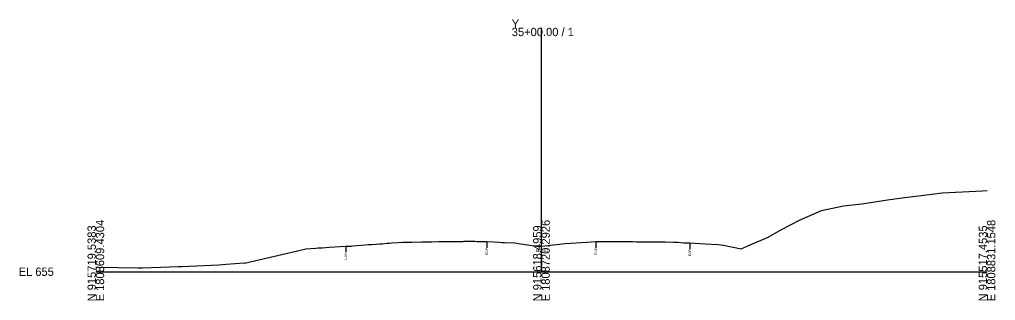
# Model space of a CAD drawing. Extents: x -26 to 3303, y -30 to 9580.
# Drawn here: x 1974.3 to 2302.8, y 4990.3 to 5085 of the extents above; entities that cross this region are included whole.
import ezdxf

# ---------------------------------------------------------------- set-up
doc = ezdxf.new("R2010")
doc.units = 0
for name, color, linetype in [('Exist Cross Section Cell', 7, 'Continuous'), ('Exist XS Center Line Elevation Label', 7, 'Continuous'), ('Exist XS Ground Line', 7, 'Continuous'), ('Old_Level_10', 7, 'Continuous')]:
    doc.layers.add(name, color=color, linetype=linetype)

msp = doc.modelspace()

# ---------------------------------------------------------------- linework, layer by layer
at = {"layer": 'Exist Cross Section Cell'}
for p, q in [((2150, 5000), (2150, 5082.17)), ((2000, 5000), (2150, 5000)), ((2150, 5000), (2300, 5000))]:
    msp.add_line(p, q, dxfattribs=at)
at = {"layer": 'Exist XS Ground Line'}
msp.add_lwpolyline([(2000, 5001.52), (2000.77, 5001.56), (2014.3, 5001.28), (2015.75, 5001.33), (2027.83, 5001.73), (2029.01, 5001.78), (2041.36, 5002.29), (2043.85, 5002.52), (2049.92, 5003.01), (2050.01, 5002.83), (2067.84, 5007.04), (2070.64, 5007.73), (2074.06, 5007.96), (2074.85, 5008.01), (2076.13, 5008.09), (2078.56, 5008.24), (2084.11, 5008.59), (2086.07, 5008.65), (2086.48, 5008.67), (2087.9, 5008.86), (2089.44, 5008.96), (2090.64, 5009.05), (2091.79, 5009.13), (2092.84, 5009.2), (2094.35, 5009.3), (2095.62, 5009.39), (2096.39, 5009.44), (2098.07, 5009.57), (2098.87, 5009.63), (2099.58, 5009.68), (2101.78, 5009.83), (2103.21, 5009.91), (2103.75, 5009.94), (2103.97, 5009.94), (2105.48, 5009.96), (2106.37, 5009.98), (2109.72, 5010.05), (2111.25, 5010.07), (2113.11, 5010.09), (2115.48, 5010.13), (2115.87, 5010.13), (2116.64, 5010.15), (2120.31, 5010.21), (2121.88, 5010.22), (2123.3, 5010.23), (2123.64, 5010.23), (2124.02, 5010.24), (2125.42, 5010.25), (2126.65, 5010.26), (2127.31, 5010.27), (2127.68, 5010.27), (2128.39, 5010.21), (2130.04, 5010.15), (2131.13, 5010.14), (2131.59, 5010.13), (2133.91, 5010.03), (2135.74, 5009.95), (2136.81, 5009.89), (2137.52, 5009.85), (2140.99, 5009.69), (2142.3, 5009.5), (2149.13, 5008.53), (2150, 5008.61), (2151.16, 5008.73), (2158.02, 5009.49), (2165.23, 5009.95), (2166.72, 5010.04), (2168.36, 5010.15), (2169.22, 5010.15), (2170.63, 5010.16), (2171.94, 5010.2), (2172.35, 5010.23), (2172.95, 5010.22), (2174.02, 5010.21), (2174.96, 5010.19), (2176, 5010.18), (2176.74, 5010.18), (2177.41, 5010.17), (2178.52, 5010.16), (2179.73, 5010.15), (2180.8, 5010.14), (2182.05, 5010.12), (2183.47, 5010.1), (2184.18, 5010.08), (2184.7, 5010.08), (2187.55, 5010.04), (2190.94, 5010.02), (2191.61, 5010.02), (2194.56, 5009.98), (2195.84, 5009.96), (2197.97, 5009.76), (2198.28, 5009.75), (2199.94, 5009.7), (2205.07, 5009.44), (2209.49, 5009.22), (2211.23, 5008.9), (2217.23, 5007.76), (2220.28, 5009.03), (2226.28, 5011.6), (2230.79, 5014.25), (2236.84, 5017.42), (2244.32, 5020.63), (2251.68, 5022.18), (2257.85, 5022.89), (2266.53, 5024.23), (2271.38, 5024.85), (2281.37, 5026.15), (2284.91, 5026.63), (2296.22, 5027.1), (2298.44, 5027.22), (2300, 5027.39)], dxfattribs=at)
at = {"layer": 'Old_Level_10'}
for p, q in [((2131.59, 5010.13), (2131.59, 5008.08)), ((2168.36, 5010.15), (2168.36, 5008.1)), ((2084.11, 5008.59), (2084.11, 5006.54)), ((2199.94, 5009.7), (2199.94, 5007.65))]:
    msp.add_line(p, q, dxfattribs=at)

# ---------------------------------------------------------------- texts
at = {"layer": 'Exist Cross Section Cell'}
for s, p in [('Y', (2140, 5082.17)), ('35+00.00 / 1', (2140, 5079.37)), ('EL 655', (1974, 4998.6))]:
    msp.add_text(s, height=2.8, dxfattribs=at).set_placement(p)
for s, p in [('E 1808609.4304', (2002.8, 4990)), ('E 1808720.2926', (2152.8, 4990)), ('E 1808831.1548', (2302.8, 4990)), ('N 915719.5383', (2000, 4990)), ('N 915618.4959', (2150, 4990)), ('N 915517.4535', (2300, 4990))]:
    msp.add_text(s, height=2.8, rotation=90, dxfattribs=at).set_placement(p)
at = {"layer": 'Exist XS Center Line Elevation Label'}
msp.add_text('663.61', height=1, dxfattribs=at).set_placement((2148.04, 5006.61))
at = {"layer": 'Old_Level_10'}
for p in [(2131.98, 5005.69), (2168.75, 5005.7), (2200.33, 5005.25), (2084.5, 5004.14)]:
    msp.add_text('EOP', height=0.787, rotation=90, dxfattribs=at).set_placement(p)

doc.saveas('drawing.dxf')
